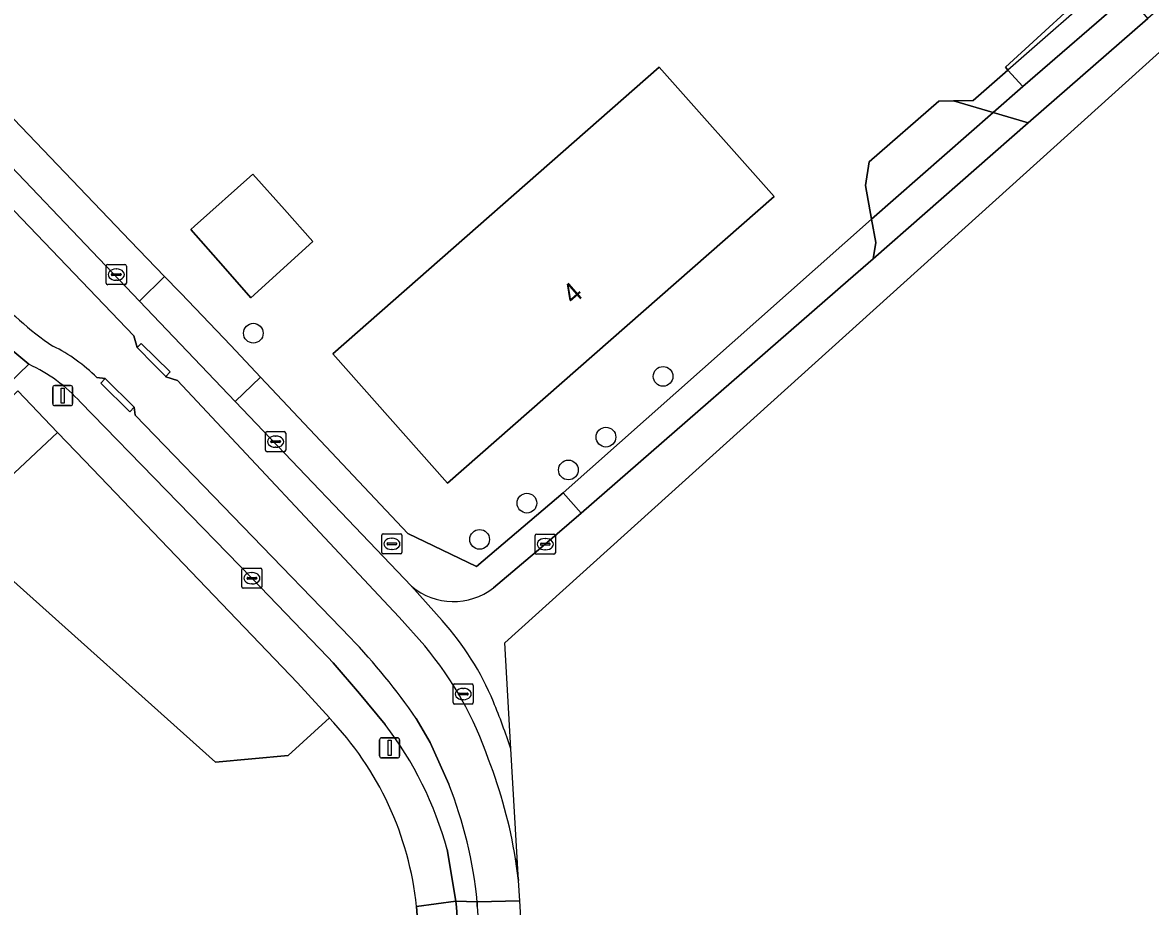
# Model space of a CAD drawing. Extents: x 156702 to 158052, y 387630 to 388992.
# Drawn here: x 157604.1 to 157660.1, y 388082.2 to 388126 of the extents above; entities that cross this region are included whole.
import ezdxf

# ---------------------------------------------------------------- set-up
doc = ezdxf.new("R2010")
doc.units = 0
for name, color, linetype in [('IMGEO_Boom', 7, 'Continuous'), ('IMGEO_Brandkraan', 7, 'Continuous'), ('IMGEO_Erf', 7, 'Continuous'), ('IMGEO_Gemengd_bos', 7, 'Continuous'), ('IMGEO_Groenvoorziening', 7, 'Continuous'), ('IMGEO_Hek', 7, 'Continuous'), ('IMGEO_Kolk', 7, 'Continuous'), ('IMGEO_Lichtmast', 7, 'Continuous'), ('IMGEO_Muur', 7, 'Continuous'), ('IMGEO_Pand', 7, 'Continuous'), ('IMGEO_Pand_nummerreeks', 7, 'Continuous'), ('IMGEO_Rijbaan_lokaal_open', 7, 'Continuous'), ('IMGEO_Rioolput', 7, 'Continuous'), ('IMGEO_Voetpad_open', 7, 'Continuous'), ('IMGEO_Waterloop', 7, 'Continuous')]:
    doc.layers.add(name, color=color, linetype=linetype)

msp = doc.modelspace()

# ---------------------------------------------------------------- linework, layer by layer
at = {"layer": 'IMGEO_Boom'}
for centre in [(157615.557, 388110.603), (157635.902, 388108.46), (157633.062, 388105.443), (157631.197, 388103.814), (157629.139, 388102.167), (157626.792, 388100.368)]:
    msp.add_circle(centre, 0.489, dxfattribs=at)
at = {"layer": 'IMGEO_Brandkraan'}
for p, q in [((157621.934, 388099.721), (157621.934, 388100.573)), ((157622.009, 388100.647), (157622.861, 388100.647)), ((157622.422, 388100.427), (157622.447, 388100.427)), ((157622.935, 388100.573), (157622.935, 388099.721)), ((157622.193, 388100.141), (157622.193, 388100.153)), ((157622.631, 388100.104), (157622.233, 388100.104)), ((157622.236, 388100.19), (157622.634, 388100.19)), ((157622.445, 388099.867), (157622.42, 388099.867)), ((157622.677, 388100.153), (157622.677, 388100.141)), ((157622.861, 388099.647), (157622.009, 388099.647))]:
    msp.add_line(p, q, dxfattribs=at)
for points in [[(157621.934, 388099.721), (157621.934, 388100.573)], [(157622.009, 388100.647), (157622.861, 388100.647)], [(157622.935, 388100.573), (157622.935, 388099.721)], [(157622.861, 388099.647), (157622.009, 388099.647)]]:
    msp.add_lwpolyline(points, dxfattribs=at)
for centre, radius, start, end in [((157622.011, 388100.571), 0.0765, 91.552, 178.448), ((157622.011, 388100.571), 0.0765, 91.552, 178.448), ((157622.859, 388100.571), 0.0765, 1.552, 88.448), ((157622.859, 388100.571), 0.0765, 1.552, 88.448), ((157622.011, 388099.723), 0.0765, 181.552, 268.448), ((157622.011, 388099.723), 0.0765, 181.552, 268.448), ((157622.233, 388100.15), 0.0403, 85.8775, 175.7526), ((157622.23, 388100.14), 0.0366, 178.938, 274.7102), ((157622.634, 388100.147), 0.043, 264.8664, 352.4533), ((157622.638, 388100.152), 0.0386, 1.7309, 96.639), ((157622.859, 388099.723), 0.0765, 271.552, 358.448), ((157622.859, 388099.723), 0.0765, 271.552, 358.448)]:
    msp.add_arc(centre, radius, start, end, dxfattribs=at)
for centre, major_axis, ratio, start_param, end_param in [((157622.421, 388100.147), (-0.387, 0.002), 0.722429, 4.712389, 7.853982), ((157622.446, 388100.147), (-0.39, 0.002), 0.717154, 1.570796, 4.712389)]:
    msp.add_ellipse(centre, major_axis=major_axis, ratio=ratio, start_param=start_param, end_param=end_param, dxfattribs=at)
at = {"layer": 'IMGEO_Erf'}
msp.add_lwpolyline([(157593.208, 388132.152), (157609.438, 388115.184), (157611.15, 388113.418), (157611.903, 388112.641), (157611.955, 388112.587), (157614.435, 388109.985), (157615.908, 388108.421), (157623.222, 388100.654), (157626.628, 388099.019), (157630.946, 388102.684), (157646.249, 388116.257), (157645.954, 388117.932), (157646.127, 388119.108), (157649.581, 388122.12), (157650.311, 388122.132), (157651.289, 388122.149), (157653.016, 388123.661), (157652.893, 388123.798), (157657.812, 388128.327)], dxfattribs=at)
for points in [[(157641.414, 388117.38), (157625.189, 388103.157), (157619.496, 388109.575), (157635.703, 388123.804)], [(157615.534, 388118.501), (157617.106, 388116.735), (157618.517, 388115.15), (157615.438, 388112.364), (157614.055, 388113.931), (157612.447, 388115.753), (157612.63, 388115.916)]]:
    msp.add_lwpolyline(points, close=True, dxfattribs=at)
at = {"layer": 'IMGEO_Gemengd_bos'}
for points in [[(157619.33, 388091.512), (157617.29, 388089.65), (157613.671, 388089.32), (157603.045, 388098.834), (157591.502, 388088.329), (157583.999, 388083.451), (157583.148, 388084.42), (157605.841, 388105.68), (157603.869, 388107.738), (157603.286, 388107.175), (157602.875, 388107.598), (157602.721, 388107.759), (157543.243, 388052.841), (157521.408, 388032.33)], [(157614.435, 388048.767), (157619.655, 388055.738), (157620.91, 388056.517), (157620.87, 388061.577), (157622.996, 388063.579), (157624.989, 388063.89), (157624.738, 388067.383), (157623.663, 388082.153)]]:
    msp.add_lwpolyline(points, dxfattribs=at)
msp.add_arc((157607.769, 388080.477), 15.982, 6.0195, 43.6666, dxfattribs=at)
at = {"layer": 'IMGEO_Groenvoorziening'}
for points in [[(157659.964, 388126.225), (157659.013, 388127.388), (157653.756, 388122.838), (157652.287, 388121.55), (157654.031, 388121.036)], [(157653.756, 388122.838), (157653.016, 388123.661), (157651.289, 388122.149), (157650.311, 388122.132), (157652.287, 388121.55)], [(157630.946, 388102.684), (157631.831, 388101.666), (157645.085, 388113.213), (157646.329, 388114.301), (157646.454, 388115.097), (157646.249, 388116.257)], [(157611.955, 388112.587), (157611.903, 388112.641), (157611.15, 388113.418), (157609.911, 388112.196), (157614.66, 388107.216), (157615.908, 388108.421), (157614.435, 388109.985)], [(157617.757, 388093.246), (157607.197, 388104.265), (157605.841, 388105.68), (157583.148, 388084.42), (157583.999, 388083.451), (157591.502, 388088.329), (157603.045, 388098.834), (157613.671, 388089.32), (157617.29, 388089.65), (157619.33, 388091.512)]]:
    msp.add_lwpolyline(points, close=True, dxfattribs=at)
at = {"layer": 'IMGEO_Hek'}
for points in [[(157658.163, 388128.17), (157653.016, 388123.661)], [(157653.016, 388123.661), (157651.289, 388122.149), (157650.311, 388122.132)], [(157650.311, 388122.132), (157649.581, 388122.12), (157646.127, 388119.108), (157645.954, 388117.932)]]:
    msp.add_lwpolyline(points, dxfattribs=at)
at = {"layer": 'IMGEO_Kolk'}
for p, q in [((157608.251, 388113.085), (157608.251, 388113.937)), ((157608.326, 388114.011), (157609.178, 388114.011)), ((157608.739, 388113.791), (157608.764, 388113.791)), ((157609.252, 388113.937), (157609.252, 388113.085)), ((157608.51, 388113.505), (157608.51, 388113.517)), ((157608.948, 388113.468), (157608.55, 388113.468)), ((157608.553, 388113.554), (157608.951, 388113.554)), ((157608.762, 388113.231), (157608.737, 388113.231)), ((157608.994, 388113.517), (157608.994, 388113.505)), ((157609.178, 388113.011), (157608.326, 388113.011)), ((157616.162, 388104.794), (157616.162, 388105.646)), ((157616.237, 388105.72), (157617.089, 388105.72)), ((157616.464, 388105.263), (157616.862, 388105.263)), ((157616.65, 388105.5), (157616.675, 388105.5)), ((157617.163, 388105.646), (157617.163, 388104.794)), ((157617.089, 388104.72), (157616.237, 388104.72)), ((157616.421, 388105.214), (157616.421, 388105.226)), ((157616.859, 388105.177), (157616.461, 388105.177)), ((157616.673, 388104.94), (157616.648, 388104.94)), ((157616.905, 388105.226), (157616.905, 388105.214)), ((157629.549, 388099.706), (157629.549, 388100.558)), ((157629.624, 388100.632), (157630.476, 388100.632)), ((157630.037, 388100.412), (157630.062, 388100.412)), ((157630.55, 388100.558), (157630.55, 388099.706)), ((157629.808, 388100.126), (157629.808, 388100.138)), ((157630.246, 388100.089), (157629.848, 388100.089)), ((157629.851, 388100.175), (157630.249, 388100.175)), ((157630.06, 388099.852), (157630.035, 388099.852)), ((157630.292, 388100.138), (157630.292, 388100.126)), ((157630.476, 388099.632), (157629.624, 388099.632)), ((157614.985, 388098.016), (157614.985, 388098.868)), ((157615.06, 388098.942), (157615.912, 388098.942)), ((157615.473, 388098.722), (157615.498, 388098.722)), ((157615.986, 388098.868), (157615.986, 388098.016)), ((157615.244, 388098.436), (157615.244, 388098.448)), ((157615.682, 388098.399), (157615.284, 388098.399)), ((157615.287, 388098.485), (157615.685, 388098.485)), ((157615.496, 388098.162), (157615.471, 388098.162)), ((157615.728, 388098.448), (157615.728, 388098.436)), ((157615.912, 388097.942), (157615.06, 388097.942))]:
    msp.add_line(p, q, dxfattribs=at)
for points in [[(157608.251, 388113.085), (157608.251, 388113.937)], [(157608.326, 388114.011), (157609.178, 388114.011)], [(157609.252, 388113.937), (157609.252, 388113.085)], [(157609.178, 388113.011), (157608.326, 388113.011)], [(157616.162, 388104.794), (157616.162, 388105.646)], [(157616.237, 388105.72), (157617.089, 388105.72)], [(157617.163, 388105.646), (157617.163, 388104.794)], [(157617.089, 388104.72), (157616.237, 388104.72)], [(157629.549, 388099.706), (157629.549, 388100.558)], [(157629.624, 388100.632), (157630.476, 388100.632)], [(157630.55, 388100.558), (157630.55, 388099.706)], [(157630.476, 388099.632), (157629.624, 388099.632)], [(157614.985, 388098.016), (157614.985, 388098.868)], [(157615.06, 388098.942), (157615.912, 388098.942)], [(157615.986, 388098.868), (157615.986, 388098.016)], [(157615.912, 388097.942), (157615.06, 388097.942)]]:
    msp.add_lwpolyline(points, dxfattribs=at)
for centre, radius, start, end in [((157608.328, 388113.935), 0.0765, 91.552, 178.448), ((157608.328, 388113.935), 0.0765, 91.552, 178.448), ((157609.176, 388113.935), 0.0765, 1.552, 88.448), ((157609.176, 388113.935), 0.0765, 1.552, 88.448), ((157608.55, 388113.514), 0.0403, 85.8775, 175.7526), ((157608.547, 388113.504), 0.0366, 178.938, 274.7102), ((157608.951, 388113.511), 0.043, 264.8664, 352.4533), ((157608.955, 388113.516), 0.0386, 1.7309, 96.639), ((157608.328, 388113.087), 0.0765, 181.552, 268.448), ((157608.328, 388113.087), 0.0765, 181.552, 268.448), ((157609.176, 388113.087), 0.0765, 271.552, 358.448), ((157609.176, 388113.087), 0.0765, 271.552, 358.448), ((157616.239, 388105.644), 0.0765, 91.552, 178.448), ((157616.239, 388105.644), 0.0765, 91.552, 178.448), ((157616.461, 388105.223), 0.0403, 85.8775, 175.7526), ((157616.866, 388105.225), 0.0386, 1.7309, 96.639), ((157617.087, 388105.644), 0.0765, 1.552, 88.448), ((157617.087, 388105.644), 0.0765, 1.552, 88.448), ((157616.239, 388104.796), 0.0765, 181.552, 268.448), ((157616.239, 388104.796), 0.0765, 181.552, 268.448), ((157616.458, 388105.213), 0.0366, 178.938, 274.7102), ((157616.862, 388105.22), 0.043, 264.8664, 352.4533), ((157617.087, 388104.796), 0.0765, 271.552, 358.448), ((157617.087, 388104.796), 0.0765, 271.552, 358.448), ((157629.626, 388100.556), 0.0765, 91.552, 178.448), ((157629.626, 388100.556), 0.0765, 91.552, 178.448), ((157630.474, 388100.556), 0.0765, 1.552, 88.448), ((157630.474, 388100.556), 0.0765, 1.552, 88.448), ((157629.626, 388099.708), 0.0765, 181.552, 268.448), ((157629.626, 388099.708), 0.0765, 181.552, 268.448), ((157629.848, 388100.135), 0.0403, 85.8775, 175.7526), ((157629.845, 388100.125), 0.0366, 178.938, 274.7102), ((157630.249, 388100.132), 0.043, 264.8664, 352.4533), ((157630.253, 388100.137), 0.0386, 1.7309, 96.639), ((157630.474, 388099.708), 0.0765, 271.552, 358.448), ((157630.474, 388099.708), 0.0765, 271.552, 358.448), ((157615.062, 388098.866), 0.0765, 91.552, 178.448), ((157615.062, 388098.866), 0.0765, 91.552, 178.448), ((157615.91, 388098.866), 0.0765, 1.552, 88.448), ((157615.91, 388098.866), 0.0765, 1.552, 88.448), ((157615.062, 388098.018), 0.0765, 181.552, 268.448), ((157615.062, 388098.018), 0.0765, 181.552, 268.448), ((157615.284, 388098.445), 0.0403, 85.8775, 175.7526), ((157615.281, 388098.435), 0.0366, 178.938, 274.7102), ((157615.685, 388098.442), 0.043, 264.8664, 352.4533), ((157615.689, 388098.447), 0.0386, 1.7309, 96.639), ((157615.91, 388098.018), 0.0765, 271.552, 358.448), ((157615.91, 388098.018), 0.0765, 271.552, 358.448)]:
    msp.add_arc(centre, radius, start, end, dxfattribs=at)
for centre, major_axis, ratio, start_param, end_param in [((157608.738, 388113.511), (-0.387, 0.002), 0.722429, 4.712389, 7.853982), ((157608.763, 388113.511), (-0.39, 0.002), 0.717154, 1.570796, 4.712389), ((157616.649, 388105.22), (-0.387, 0.002), 0.722429, 4.712389, 7.853982), ((157616.674, 388105.22), (-0.39, 0.002), 0.717154, 1.570796, 4.712389), ((157630.036, 388100.132), (-0.387, 0.002), 0.722429, 4.712389, 7.853982), ((157630.061, 388100.132), (-0.39, 0.002), 0.717154, 1.570796, 4.712389), ((157615.472, 388098.442), (-0.387, 0.002), 0.722429, 4.712389, 7.853982), ((157615.497, 388098.442), (-0.39, 0.002), 0.717154, 1.570796, 4.712389)]:
    msp.add_ellipse(centre, major_axis=major_axis, ratio=ratio, start_param=start_param, end_param=end_param, dxfattribs=at)
at = {"layer": 'IMGEO_Lichtmast'}
for p, q in [((157605.597, 388107.106), (157605.597, 388107.906)), ((157605.597, 388107.906), (157605.597, 388107.106)), ((157605.697, 388108.006), (157606.487, 388108.006)), ((157606.487, 388108.006), (157605.697, 388108.006)), ((157606.587, 388107.906), (157606.587, 388107.106)), ((157606.587, 388107.106), (157606.587, 388107.906)), ((157606.487, 388107.006), (157605.697, 388107.006)), ((157605.697, 388107.006), (157606.487, 388107.006)), ((157621.826, 388089.622), (157621.826, 388090.422)), ((157621.826, 388090.422), (157621.826, 388089.622)), ((157621.926, 388090.522), (157622.716, 388090.522)), ((157622.716, 388090.522), (157621.926, 388090.522)), ((157622.816, 388090.422), (157622.816, 388089.622)), ((157622.816, 388089.622), (157622.816, 388090.422)), ((157622.716, 388089.522), (157621.926, 388089.522)), ((157621.926, 388089.522), (157622.716, 388089.522))]:
    msp.add_line(p, q, dxfattribs=at)
for points in [[(157606.017, 388107.881), (157606.167, 388107.881), (157606.167, 388107.131), (157606.017, 388107.131), (157606.017, 388107.881)], [(157622.246, 388090.397), (157622.396, 388090.397), (157622.396, 388089.647), (157622.246, 388089.647), (157622.246, 388090.397)]]:
    msp.add_lwpolyline(points, dxfattribs=at)
for centre, start, end in [((157605.697, 388107.906), 90, 180), ((157605.697, 388107.906), 90, 180), ((157606.487, 388107.906), 0, 90), ((157606.487, 388107.906), 360, 90), ((157605.697, 388107.106), 180, 270), ((157605.697, 388107.106), 180, 270), ((157606.487, 388107.106), 270, 0), ((157606.487, 388107.106), 270, 0), ((157621.926, 388090.422), 90, 180), ((157621.926, 388090.422), 90, 180), ((157622.716, 388090.422), 0, 90), ((157622.716, 388090.422), 360, 90), ((157621.926, 388089.622), 180, 270), ((157621.926, 388089.622), 180, 270), ((157622.716, 388089.622), 270, 0), ((157622.716, 388089.622), 270, 0)]:
    msp.add_arc(centre, 0.1, start, end, dxfattribs=at)
at = {"layer": 'IMGEO_Muur'}
for points in [[(157609.788, 388109.895), (157610.633, 388109.036), (157611.207, 388108.452), (157611.432, 388108.678), (157609.989, 388110.099)], [(157608.205, 388108.355), (157607.979, 388108.127), (157609.418, 388106.701), (157609.641, 388106.929), (157609.641, 388106.932)]]:
    msp.add_lwpolyline(points, close=True, dxfattribs=at)
at = {"layer": 'IMGEO_Pand'}
for points in [[(157625.189, 388103.157), (157641.414, 388117.38), (157635.703, 388123.804), (157619.496, 388109.575)], [(157618.517, 388115.15), (157617.106, 388116.735), (157615.534, 388118.501), (157612.63, 388115.916), (157612.447, 388115.753), (157614.055, 388113.931), (157615.438, 388112.364)]]:
    msp.add_lwpolyline(points, close=True, dxfattribs=at)
at = {"layer": 'IMGEO_Rijbaan_lokaal_open'}
for points in [[(157624.063, 388095.085), (157622.801, 388096.503), (157622.266, 388097.074), (157611.799, 388108.253), (157611.22, 388108.439), (157611.207, 388108.452), (157610.633, 388109.036), (157609.788, 388109.895), (157609.631, 388110.47), (157569.611, 388152.266), (157505.252, 388219.445), (157502.666, 388217.076), (157520.881, 388198.047), (157571.193, 388145.504), (157602.434, 388112.73)], [(157520.881, 388198.047), (157502.666, 388217.076), (157501.5, 388216.007), (157502.813, 388214.652), (157503.415, 388215.215), (157506.471, 388212.039), (157505.936, 388211.53), (157515.137, 388201.917), (157519.764, 388197.104), (157530.97, 388185.39), (157541.858, 388174.01), (157557.021, 388158.183), (157559.496, 388155.588), (157566.169, 388148.651), (157574.344, 388140.111), (157580.64, 388133.535), (157588.386, 388125.454), (157602.101, 388110.987), (157604.416, 388109.059)], [(157628.345, 388089.973), (157628.035, 388095.238), (157730.293, 388187.485), (157729.533, 388188.285), (157726.48, 388185.589), (157719.501, 388179.05), (157705.796, 388166.305), (157703.948, 388164.689), (157659.964, 388126.225), (157654.031, 388121.036), (157646.329, 388114.301), (157645.085, 388113.213), (157631.831, 388101.666), (157630.049, 388100.133), (157627.477, 388097.962)], [(157569.611, 388152.266), (157609.631, 388110.47), (157609.788, 388109.895), (157609.989, 388110.099), (157611.432, 388108.678), (157611.207, 388108.452), (157611.22, 388108.439), (157611.799, 388108.253), (157622.266, 388097.074), (157622.801, 388096.503), (157624.063, 388095.085)], [(157624.93, 388096.337), (157623.408, 388098.043), (157614.66, 388107.216), (157609.911, 388112.196), (157591.786, 388131.202)], [(157620.38, 388095.484), (157609.691, 388106.528), (157609.641, 388106.929), (157609.418, 388106.701), (157607.979, 388108.127), (157608.205, 388108.355), (157607.788, 388108.401)], [(157607.788, 388108.401), (157608.205, 388108.355), (157609.641, 388106.932), (157609.641, 388106.929), (157609.691, 388106.528), (157620.38, 388095.484)], [(157606.976, 388107.174), (157615.487, 388098.443), (157619.255, 388094.518), (157619.517, 388094.245), (157620.833, 388092.727), (157622.099, 388091.175)], [(157623.408, 388098.043), (157624.93, 388096.337)], [(157625.259, 388088.225), (157624.328, 388090.29), (157623.646, 388091.476)], [(157623.646, 388091.476), (157624.328, 388090.29), (157625.259, 388088.225)], [(157628.577, 388084.514), (157628.728, 388083.446), (157628.345, 388089.973)], [(157625.177, 388084.972), (157625.617, 388082.408), (157626.67, 388082.386)], [(157628.728, 388083.446), (157628.577, 388084.514)], [(157626.67, 388082.386), (157628.788, 388082.423), (157628.728, 388083.446)], [(157626.673, 388082.152), (157626.67, 388082.386), (157625.617, 388082.408), (157625.649, 388082.108), (157625.747, 388080.633), (157627.187, 388060.606), (157628.878, 388037.453), (157628.892, 388036.942), (157629.909, 388022.812), (157630.335, 388017.158), (157631.131, 388007.154), (157632.046, 388000.076), (157632.089, 387999.743), (157632.294, 387998.512), (157632.794, 387996.132), (157633.504, 387993.806), (157634.419, 387991.553), (157635.532, 387989.39), (157635.815, 387988.907), (157636.464, 387987.804)], [(157653.402, 387971.074), (157641.25, 387984.74), (157634.522, 387998.317), (157633.009, 388010.637), (157628.788, 388082.423), (157626.67, 388082.386), (157626.673, 388082.152), (157628.231, 388060.388), (157631.368, 388017.187), (157632.02, 388009.07), (157632.319, 388005.936), (157632.839, 388001.765), (157633.123, 388000), (157633.473, 387997.823), (157634.096, 387995.205), (157634.191, 387994.819)]]:
    msp.add_lwpolyline(points, dxfattribs=at)
for points in [[(157652.287, 388121.55), (157650.311, 388122.132), (157649.581, 388122.12), (157646.127, 388119.108), (157645.954, 388117.932), (157646.249, 388116.257)], [(157646.249, 388116.257), (157646.454, 388115.097), (157646.329, 388114.301), (157654.031, 388121.036), (157652.287, 388121.55)]]:
    msp.add_lwpolyline(points, close=True, dxfattribs=at)
for centre, radius, start, end in [((157615.745, 388124.759), 17.941, 222.1048, 235.6051), ((157615.745, 388124.759), 17.941, 222.1048, 235.6051), ((157602.175, 388102.837), 7.904, 44.7474, 64.237), ((157602.175, 388102.837), 7.904, 44.7474, 64.237), ((157601.16, 388101.957), 7.813, 41.8961, 65.3734), ((157625.493, 388100.537), 3.251, 230.1075, 307.6117), ((157614.53, 388086.942), 14.015, 22.5172, 42.0951), ((157614.53, 388086.942), 14.015, 22.5172, 42.0951), ((157596.575, 388072.752), 32.915, 34.6711, 43.6801), ((157596.575, 388072.752), 32.915, 34.6711, 43.6801), ((157610.663, 388083.841), 17.492, 18.6976, 39.9986), ((157610.663, 388083.841), 17.492, 18.6976, 39.9986), ((157590.562, 388077.271), 39.861, 18.5823, 22.1648), ((157590.562, 388077.271), 39.861, 18.5823, 22.1648), ((157607.919, 388080.274), 17.886, 15.2294, 37.5529), ((157604.3, 388080.548), 24.598, 9.2775, 21.2131), ((157604.3, 388080.548), 24.598, 9.2775, 21.2131), ((157605.01, 388080.242), 21.766, 5.6535, 21.5168), ((157605.01, 388080.242), 21.766, 5.6535, 21.5168)]:
    msp.add_arc(centre, radius, start, end, dxfattribs=at)
at = {"layer": 'IMGEO_Rioolput'}
for p, q in [((157625.475, 388092.268), (157625.475, 388093.12)), ((157625.55, 388093.194), (157626.402, 388093.194)), ((157625.963, 388092.974), (157625.988, 388092.974)), ((157626.476, 388093.12), (157626.476, 388092.268)), ((157625.734, 388092.688), (157625.734, 388092.7)), ((157626.172, 388092.651), (157625.774, 388092.651)), ((157625.777, 388092.737), (157626.175, 388092.737)), ((157625.986, 388092.414), (157625.961, 388092.414)), ((157626.218, 388092.7), (157626.218, 388092.688)), ((157626.402, 388092.194), (157625.55, 388092.194))]:
    msp.add_line(p, q, dxfattribs=at)
for points in [[(157625.475, 388092.268), (157625.475, 388093.12)], [(157625.55, 388093.194), (157626.402, 388093.194)], [(157626.476, 388093.12), (157626.476, 388092.268)], [(157626.402, 388092.194), (157625.55, 388092.194)]]:
    msp.add_lwpolyline(points, dxfattribs=at)
for centre, radius, start, end in [((157625.552, 388093.118), 0.0765, 91.552, 178.448), ((157625.552, 388093.118), 0.0765, 91.552, 178.448), ((157626.4, 388093.118), 0.0765, 1.552, 88.448), ((157626.4, 388093.118), 0.0765, 1.552, 88.448), ((157625.774, 388092.697), 0.0403, 85.8775, 175.7526), ((157625.771, 388092.687), 0.0366, 178.938, 274.7102), ((157626.175, 388092.694), 0.043, 264.8664, 352.4533), ((157626.179, 388092.699), 0.0386, 1.7309, 96.639), ((157625.552, 388092.27), 0.0765, 181.552, 268.448), ((157625.552, 388092.27), 0.0765, 181.552, 268.448), ((157626.4, 388092.27), 0.0765, 271.552, 358.448), ((157626.4, 388092.27), 0.0765, 271.552, 358.448)]:
    msp.add_arc(centre, radius, start, end, dxfattribs=at)
for centre, major_axis, ratio, start_param, end_param in [((157625.962, 388092.694), (-0.387, 0.002), 0.722429, 4.712389, 7.853982), ((157625.987, 388092.694), (-0.39, 0.002), 0.717154, 1.570796, 4.712389)]:
    msp.add_ellipse(centre, major_axis=major_axis, ratio=ratio, start_param=start_param, end_param=end_param, dxfattribs=at)
at = {"layer": 'IMGEO_Voetpad_open'}
for points in [[(157574.214, 388152.004), (157573.82, 388152.417), (157572.789, 388153.497), (157570.562, 388155.83), (157565.368, 388161.238), (157564.437, 388160.383), (157564.295, 388160.496), (157564.008, 388160.23), (157569.341, 388154.667), (157573.012, 388150.836), (157577.621, 388146.005), (157591.786, 388131.202), (157609.911, 388112.196), (157611.15, 388113.418), (157609.438, 388115.184), (157593.208, 388132.152)], [(157588.386, 388125.454), (157587.035, 388124.121), (157602.721, 388107.759), (157602.875, 388107.598), (157604.416, 388109.059), (157602.101, 388110.987)], [(157625.747, 388080.633), (157625.649, 388082.108), (157625.617, 388082.408), (157623.663, 388082.153), (157624.738, 388067.383), (157624.989, 388063.89), (157625.236, 388060.439), (157626.073, 388048.976), (157626.962, 388036.8), (157627.871, 388036.867), (157628.892, 388036.942), (157628.878, 388037.453), (157627.187, 388060.606)]]:
    msp.add_lwpolyline(points, close=True, dxfattribs=at)
for points in [[(157604.416, 388109.059), (157602.875, 388107.598), (157603.286, 388107.175), (157603.869, 388107.738), (157605.841, 388105.68), (157607.197, 388104.265), (157617.757, 388093.246), (157619.33, 388091.512)], [(157615.908, 388108.421), (157614.66, 388107.216), (157623.408, 388098.043)], [(157627.477, 388097.962), (157630.049, 388100.133), (157631.831, 388101.666), (157630.946, 388102.684), (157626.628, 388099.019), (157623.222, 388100.654), (157615.908, 388108.421)], [(157619.517, 388094.245), (157619.255, 388094.518), (157615.487, 388098.443), (157606.976, 388107.174)], [(157622.099, 388091.175), (157620.833, 388092.727), (157619.517, 388094.245)], [(157623.663, 388082.153), (157625.617, 388082.408), (157625.177, 388084.972)]]:
    msp.add_lwpolyline(points, dxfattribs=at)
for centre, radius, start, end in [((157601.16, 388101.957), 7.813, 41.8961, 65.3734), ((157625.493, 388100.537), 3.251, 230.1075, 307.6117), ((157607.769, 388080.477), 15.982, 6.0195, 43.6666), ((157607.919, 388080.274), 17.886, 15.2294, 37.5529)]:
    msp.add_arc(centre, radius, start, end, dxfattribs=at)
at = {"layer": 'IMGEO_Waterloop'}
msp.add_lwpolyline([(157662.185, 388130.133), (157661.121, 388131.696), (157659.334, 388130.172), (157659.097, 388129.872), (157658.038, 388128.535), (157657.812, 388128.327), (157652.893, 388123.798), (157653.016, 388123.661), (157653.756, 388122.838), (157659.013, 388127.388)], close=True, dxfattribs=at)

# ---------------------------------------------------------------- texts
at = {"layer": 'IMGEO_Pand_nummerreeks'}
msp.add_text('4', height=1, rotation=41.2381, dxfattribs=at).set_placement((157631.434, 388111.982))

doc.saveas('drawing.dxf')
